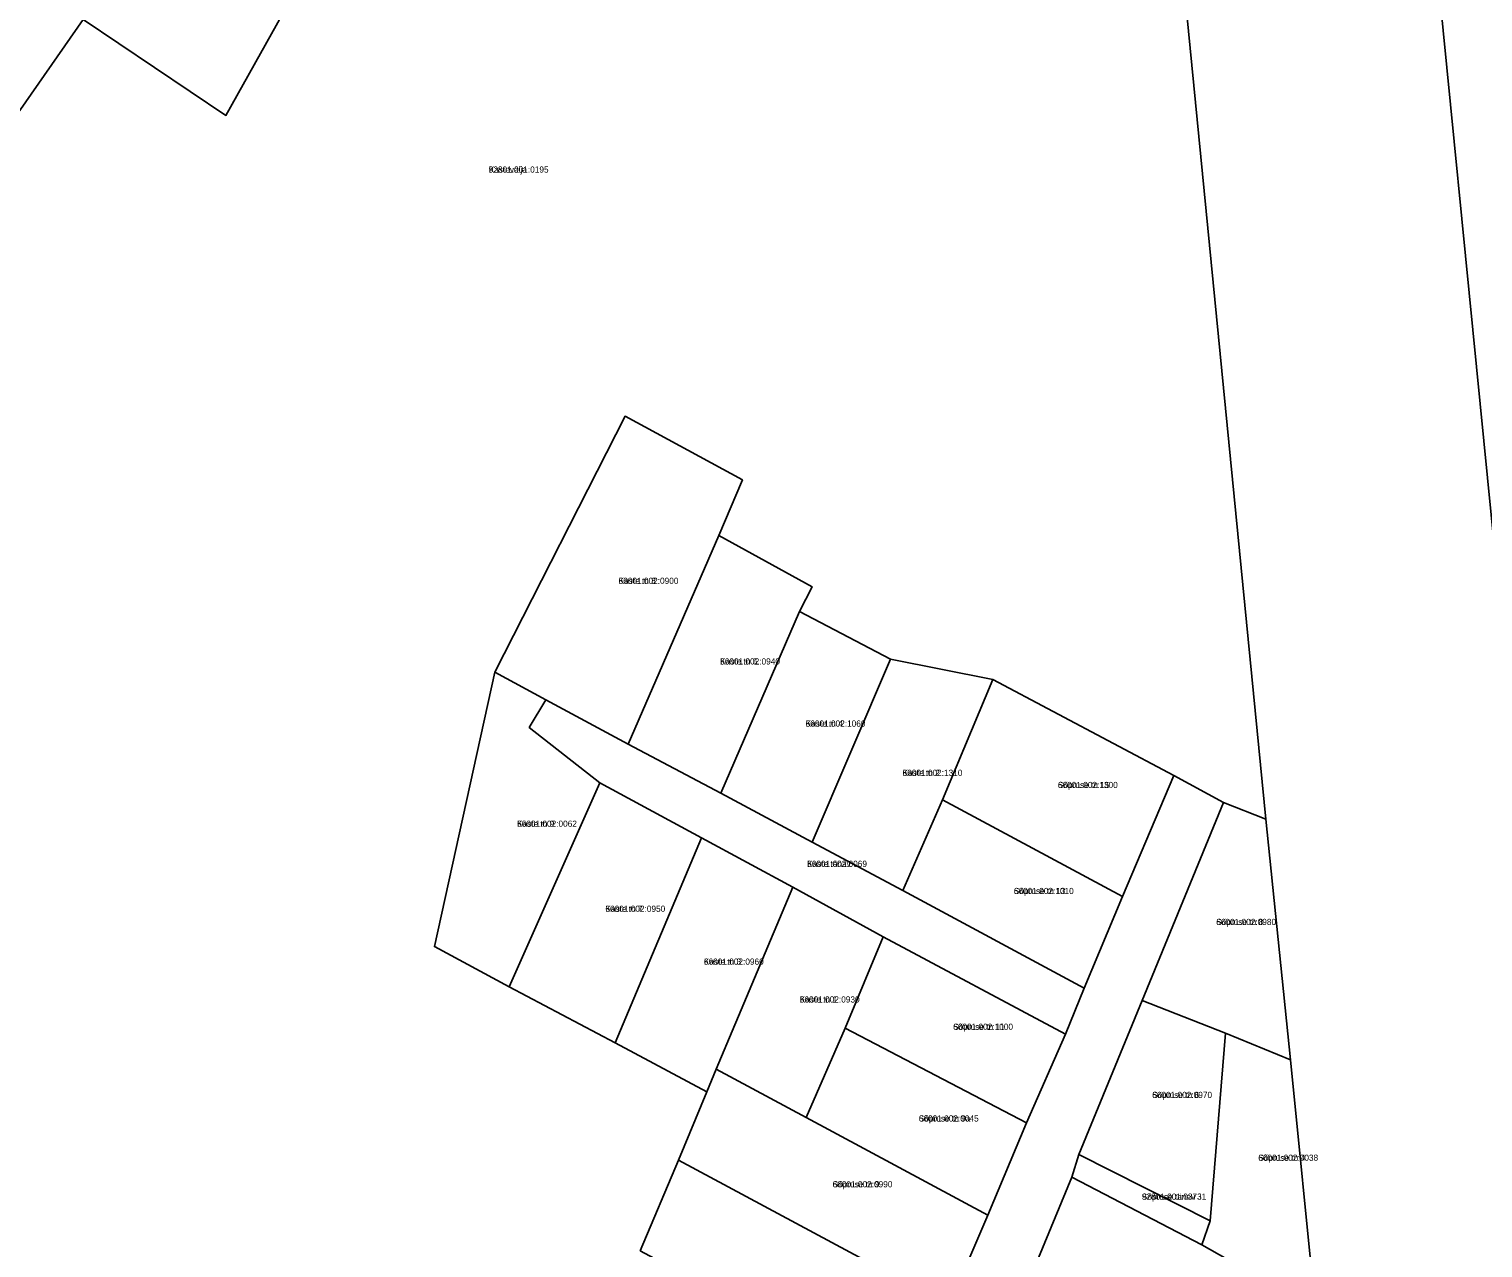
# Model space of a CAD drawing. Extents: x 615668 to 650289, y 6528908 to 6565939.
# Drawn here: x 628558.7 to 628910.9, y 6541187 to 6541482.2 of the extents above; entities that cross this region are included whole.
import ezdxf

# ---------------------------------------------------------------- set-up
doc = ezdxf.new("R2010")
doc.units = 0
for name, color, linetype in [('L_AADRESS', 7, 'Continuous'), ('PIIR', 7, 'Continuous'), ('TUNNUS', 7, 'Continuous')]:
    doc.layers.add(name, color=color, linetype=linetype)

msp = doc.modelspace()

# ---------------------------------------------------------------- linework, layer by layer
at = {"layer": 'PIIR'}
for points in [[(629001.31, 6542360.86), (629157.9, 6542209.16), (628973.08, 6541802.39), (628943.17, 6541728.18), (628935.75, 6541698.29), (628931.37, 6541665.01), (628927.68, 6541602.11), (628927.86, 6541571), (628928.15, 6541535.89), (628930.73, 6541478.26), (628930.75, 6541430.33), (628923.56, 6541305.19), (628924.04, 6541293.04), (628920.03, 6541292.88), (628889.74, 6541598.48), (628840.04, 6542104.37), (628839.61, 6542108.51), (628832.75, 6542177.13), (628846.54, 6542192.17), (628891.62, 6542241.3)], [(628488.73, 6541475.84), (628521.7, 6541520.73), (628571.8, 6541484.58), (628538.87, 6541437.5)], [(628671.51, 6541326.43), (628703.05, 6541388.44), (628731.48, 6541373.04), (628725.8, 6541359.54), (628703.82, 6541309.05), (628683.85, 6541319.76)], [(628703.82, 6541309.05), (628725.8, 6541359.54), (628748.36, 6541347.15), (628745.35, 6541341.14), (628726.23, 6541297.17)], [(628726.23, 6541297.17), (628745.35, 6541341.14), (628767.4, 6541329.61), (628748.4, 6541285.3)], [(628748.4, 6541285.3), (628767.4, 6541329.61), (628792.19, 6541324.64), (628779.97, 6541295.52), (628770.37, 6541273.6)], [(628671.51, 6541326.43), (628683.85, 6541319.76), (628679.85, 6541313.06), (628696.93, 6541299.62), (628675.01, 6541250.23), (628656.86, 6541260)], [(628779.97, 6541295.52), (628792.19, 6541324.64), (628835.98, 6541301.4), (628823.56, 6541272.11)], [(628683.85, 6541319.76), (628703.82, 6541309.05), (628726.23, 6541297.17), (628748.4, 6541285.3), (628770.37, 6541273.6), (628814.28, 6541249.87), (628809.78, 6541238.8), (628765.61, 6541262.34), (628743.69, 6541274.38), (628721.57, 6541286.34), (628696.93, 6541299.62), (628679.85, 6541313.06)], [(628675.01, 6541250.23), (628696.93, 6541299.62), (628721.57, 6541286.34), (628700.64, 6541236.66)], [(628770.37, 6541273.6), (628779.97, 6541295.52), (628823.56, 6541272.11), (628814.28, 6541249.87)], [(628828.33, 6541246.92), (628848.07, 6541294.86), (628858.27, 6541290.82), (628864.26, 6541232.55), (628848.54, 6541238.97)], [(628700.64, 6541236.66), (628721.57, 6541286.34), (628743.69, 6541274.38), (628725.17, 6541230.25), (628722.88, 6541224.79)], [(628725.17, 6541230.25), (628743.69, 6541274.38), (628765.61, 6541262.34), (628756.35, 6541240.26), (628746.94, 6541218.58)], [(628756.35, 6541240.26), (628765.61, 6541262.34), (628809.78, 6541238.8), (628800.3, 6541217.28)], [(628813.02, 6541209.59), (628828.33, 6541246.92), (628848.54, 6541238.97), (628844.85, 6541193.56)], [(628756.35, 6541240.26), (628800.3, 6541217.28), (628790.93, 6541194.94), (628746.94, 6541218.58)], [(628864.26, 6541232.55), (628870.17, 6541173.46), (628848.91, 6541184.3), (628842.78, 6541187.73), (628844.85, 6541193.56), (628848.54, 6541238.97)], [(628722.88, 6541224.79), (628725.17, 6541230.25), (628746.94, 6541218.58), (628790.93, 6541194.94), (628781.6, 6541173.08), (628716.01, 6541208.23)], [(628706.75, 6541186.25), (628716.01, 6541208.23), (628781.6, 6541173.08), (628772.36, 6541151.15)], [(628844.85, 6541193.56), (628842.78, 6541187.73), (628811.3, 6541204.12), (628813.02, 6541209.59)], [(628799.21, 6541174.81), (628811.3, 6541204.12), (628842.78, 6541187.73), (628848.91, 6541184.3), (628842.19, 6541150.5)]]:
    msp.add_lwpolyline(points, close=True, dxfattribs=at)
for points in [[(628538.87, 6541437.5), (628571.8, 6541484.58), (628606.36, 6541461.33), (628718.94, 6541662.68)], [(628718.94, 6541662.68), (628606.36, 6541461.33), (628571.8, 6541484.58)], [(628889.74, 6541598.48), (628920.03, 6541292.88)], [(628830.6, 6541573.16), (628858.27, 6541290.82), (628848.07, 6541294.86), (628835.98, 6541301.4), (628792.19, 6541324.64), (628767.4, 6541329.61), (628745.35, 6541341.14), (628748.36, 6541347.15), (628725.8, 6541359.54), (628731.48, 6541373.04), (628703.05, 6541388.44), (628671.51, 6541326.43), (628656.86, 6541260), (628675.01, 6541250.23), (628700.64, 6541236.66), (628722.88, 6541224.79), (628716.01, 6541208.23), (628706.75, 6541186.25)], [(628921.02, 6540630.42), (628902.98, 6540824.17), (628905.67, 6540823.4), (628902.67, 6540848.75), (628901.58, 6540911.37), (628912.47, 6540905.84), (628910.77, 6540923.2), (628905.6, 6540974.79), (628902.96, 6541001.3), (628885.89, 6541016.69), (628880.16, 6541066.65), (628877.8, 6541098.36), (628895.41, 6541099.44), (628894.8, 6541110.01), (628876.66, 6541108.78), (628872.17, 6541148.91), (628870.17, 6541173.46), (628864.26, 6541232.55), (628858.27, 6541290.82), (628830.6, 6541573.16)], [(628781.6, 6541173.08), (628790.93, 6541194.94), (628800.3, 6541217.28), (628809.78, 6541238.8), (628814.28, 6541249.87), (628823.56, 6541272.11), (628835.98, 6541301.4), (628848.07, 6541294.86), (628828.33, 6541246.92), (628813.02, 6541209.59), (628811.3, 6541204.12), (628799.21, 6541174.81)]]:
    msp.add_lwpolyline(points, dxfattribs=at)

# ---------------------------------------------------------------- texts
at = {"layer": 'L_AADRESS'}
for s, p in [('Kastevälja', (628670.03, 6541447.45)), ('Kaste tn 8', (628701.49, 6541347.84)), ('Kaste tn 6', (628726.09, 6541328.31)), ('Kaste tn 4', (628746.81, 6541313.26)), ('Kaste tn 2', (628770.29, 6541301.33)), ('Sõpruse tn 15', (628807.93, 6541298.38)), ('Kaste tn 9', (628676.89, 6541289)), ('Kaste tänav', (628747.17, 6541279.28)), ('Sõpruse tn 13', (628797.26, 6541272.7)), ('Kaste tn 7', (628698.29, 6541268.4)), ('Sõpruse tn 8', (628846.29, 6541265.2)), ('Kaste tn 3', (628722.16, 6541255.59)), ('Kaste tn 1', (628745.39, 6541246.43)), ('Sõpruse tn 11', (628782.55, 6541239.81)), ('Sõpruse tn 6', (628830.78, 6541223.3)), ('Sõpruse tn 9a', (628774.23, 6541217.6)), ('Sõpruse tn 4', (628856.48, 6541208.09)), ('Sõpruse tn 9', (628753.34, 6541201.66)), ('Sõpruse tänav J1', (628828.26, 6541198.66))]:
    msp.add_text(s, height=1.5, dxfattribs=at).set_placement(p)
at = {"layer": 'TUNNUS'}
for s, p in [('92801:001:0195', (628670.03, 6541447.45)), ('66001:002:0900', (628701.49, 6541347.84)), ('66001:002:0940', (628726.09, 6541328.31)), ('66001:002:1060', (628746.81, 6541313.26)), ('66001:002:1310', (628770.29, 6541301.33)), ('66001:002:1300', (628807.93, 6541298.38)), ('66001:002:0062', (628676.89, 6541289)), ('66001:002:0069', (628747.17, 6541279.28)), ('66001:002:1010', (628797.26, 6541272.7)), ('66001:002:0950', (628698.29, 6541268.4)), ('66001:002:0980', (628846.29, 6541265.2)), ('66001:002:0960', (628722.16, 6541255.59)), ('66001:002:0930', (628745.39, 6541246.43)), ('66001:002:1000', (628782.55, 6541239.81)), ('66001:002:0970', (628830.78, 6541223.3)), ('66001:002:0045', (628774.23, 6541217.6)), ('66001:002:0038', (628856.48, 6541208.09)), ('66001:002:0990', (628753.34, 6541201.66)), ('92801:001:0373', (628828.26, 6541198.66))]:
    msp.add_text(s, height=1.5, dxfattribs=at).set_placement(p)

doc.saveas('drawing.dxf')
